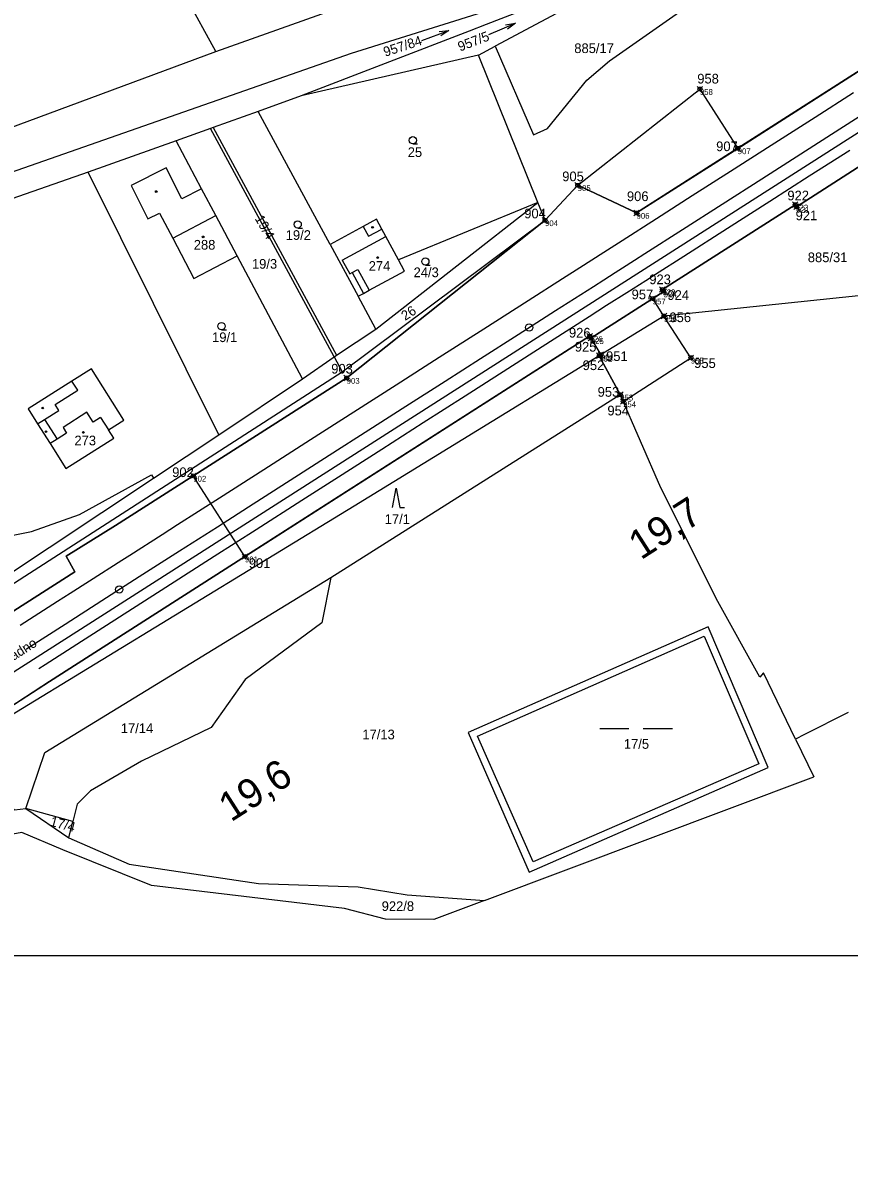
# Model space of a CAD drawing. Extents: x -752184 to -751416, y -1028299 to -1027836.
# Drawn here: x -751817.4 to -751646.8, y -1028233.3 to -1027995.9 of the extents above; entities that cross this region are included whole.
import ezdxf

# ---------------------------------------------------------------- set-up
doc = ezdxf.new("R2010")
doc.units = 0
for name, color, linetype in [('02_Osa_koleje', 7, 'Continuous'), ('03_Staničení', 7, 'Continuous'), ('Dočasné zábory', 7, 'Continuous'), ('Obvod stavby', 7, 'Continuous'), ('Vrstva 4', 7, 'Continuous'), ('Vrstva 53', 7, 'Continuous'), ('Vrstva 55', 7, 'Continuous'), ('Vrstva 56', 7, 'Continuous'), ('Vrstva 57', 7, 'Continuous'), ('Vrstva 58', 7, 'Continuous'), ('Vrstva 59', 7, 'Continuous'), ('Vrstva 60', 7, 'Continuous'), ('Vrstva 63', 7, 'Continuous'), ('VYT-BODY', 7, 'Continuous')]:
    doc.layers.add(name, color=color, linetype=linetype)

msp = doc.modelspace()

# ---------------------------------------------------------------- linework, layer by layer
at = {"layer": '02_Osa_koleje'}
for p, q in [((-751653.82, -1028015.29), (-751645.91, -1028010.23)), ((-751648.69, -1028017.73), (-751640.92, -1028012.76)), ((-751662.87, -1028021.07), (-751653.82, -1028015.29)), ((-751656.74, -1028022.88), (-751648.69, -1028017.73)), ((-751671.32, -1028026.46), (-751662.87, -1028021.07)), ((-751664.8, -1028028.03), (-751656.74, -1028022.88)), ((-751655.05, -1028027.47), (-751646.64, -1028022.11)), ((-751679.23, -1028031.51), (-751671.32, -1028026.46)), ((-751663.19, -1028032.68), (-751655.05, -1028027.47)), ((-751673, -1028033.27), (-751664.8, -1028028.03)), ((-751686.59, -1028036.23), (-751679.23, -1028031.51)), ((-751671.92, -1028038.25), (-751663.19, -1028032.68)), ((-751681.21, -1028038.52), (-751673, -1028033.27)), ((-751693.69, -1028040.78), (-751686.59, -1028036.23)), ((-751688.98, -1028043.49), (-751681.21, -1028038.52)), ((-751680.91, -1028044.01), (-751671.92, -1028038.25)), ((-751697.47, -1028043.2), (-751693.69, -1028040.78)), ((-751702.42, -1028046.37), (-751697.47, -1028043.2)), ((-751691.1, -1028044.85), (-751688.98, -1028043.49)), ((-751686.82, -1028047.78), (-751680.91, -1028044.01)), ((-751705.97, -1028048.65), (-751702.42, -1028046.37)), ((-751695.1, -1028047.41), (-751693.57, -1028046.42)), ((-751693.57, -1028046.42), (-751691.1, -1028044.85)), ((-751713.11, -1028053.22), (-751705.97, -1028048.65)), ((-751699.61, -1028050.29), (-751697.44, -1028048.9)), ((-751697.44, -1028048.9), (-751695.1, -1028047.41)), ((-751692.69, -1028051.52), (-751688.81, -1028049.05)), ((-751688.81, -1028049.05), (-751686.82, -1028047.78)), ((-751707.41, -1028055.27), (-751699.61, -1028050.29)), ((-751696.88, -1028054.2), (-751692.69, -1028051.52)), ((-751722.23, -1028059.04), (-751713.11, -1028053.22)), ((-751715.15, -1028060.22), (-751707.41, -1028055.27)), ((-751700.46, -1028056.5), (-751696.88, -1028054.2)), ((-751708.45, -1028061.62), (-751700.46, -1028056.5)), ((-751731.44, -1028064.93), (-751722.23, -1028059.04)), ((-751722.91, -1028065.18), (-751715.15, -1028060.22)), ((-751717.26, -1028067.26), (-751708.45, -1028061.62)), ((-751740.37, -1028070.64), (-751731.44, -1028064.93)), ((-751730.24, -1028069.87), (-751722.91, -1028065.18)), ((-751726.12, -1028072.93), (-751717.26, -1028067.26)), ((-751749.1, -1028076.23), (-751740.37, -1028070.64)), ((-751738.35, -1028075.06), (-751730.24, -1028069.87)), ((-751734.76, -1028078.44), (-751726.12, -1028072.93)), ((-751746.01, -1028079.96), (-751738.35, -1028075.06)), ((-751758.04, -1028081.94), (-751749.1, -1028076.23)), ((-751754.17, -1028085.18), (-751746.01, -1028079.96)), ((-751743.32, -1028083.91), (-751734.76, -1028078.44)), ((-751767.69, -1028088.11), (-751758.04, -1028081.94)), ((-751752.24, -1028089.62), (-751743.32, -1028083.91)), ((-751762.21, -1028090.32), (-751754.17, -1028085.18)), ((-751776.82, -1028093.96), (-751767.69, -1028088.11)), ((-751759.86, -1028094.49), (-751752.24, -1028089.62)), ((-751769.91, -1028095.24), (-751762.21, -1028090.32)), ((-751785.51, -1028099.52), (-751776.82, -1028093.96)), ((-751777.26, -1028099.94), (-751769.91, -1028095.24)), ((-751769.24, -1028100.51), (-751759.86, -1028094.49)), ((-751795.35, -1028105.81), (-751788.71, -1028101.56)), ((-751788.71, -1028101.56), (-751785.51, -1028099.52)), ((-751785.09, -1028104.95), (-751777.26, -1028099.94)), ((-751777.92, -1028106.05), (-751769.24, -1028100.51)), ((-751796.99, -1028106.86), (-751795.35, -1028105.81)), ((-751793.41, -1028110.27), (-751785.09, -1028104.95)), ((-751787.91, -1028112.43), (-751777.92, -1028106.05)), ((-751803.67, -1028111.13), (-751796.99, -1028106.86)), ((-751801.11, -1028115.2), (-751793.41, -1028110.27)), ((-751807.69, -1028113.7), (-751803.67, -1028111.13)), ((-751797.49, -1028118.58), (-751787.91, -1028112.43)), ((-751818.04, -1028120.32), (-751810.27, -1028115.34)), ((-751810.27, -1028115.35), (-751807.69, -1028113.7)), ((-751808.72, -1028120.07), (-751801.11, -1028115.2)), ((-751816.72, -1028125.18), (-751808.72, -1028120.07)), ((-751806.31, -1028124.21), (-751797.49, -1028118.58)), ((-751816.74, -1028125.19), (-751816.72, -1028125.18)), ((-751812.84, -1028128.4), (-751806.31, -1028124.21)), ((-751814.16, -1028129.24), (-751812.84, -1028128.4))]:
    msp.add_line(p, q, dxfattribs=at)
at = {"layer": '03_Staničení'}
for centre in [(-751712.88, -1028058.77), (-751797.54, -1028112.91)]:
    msp.add_circle(centre, 0.75, dxfattribs=at)
at = {"layer": 'Dočasné zábory'}
for points in [[(-751702.85, -1028029.39), (-751677.63, -1028009.51), (-751669.8, -1028021.76)], [(-751700.15, -1028061), (-751698.06, -1028064.4), (-751698.4, -1028064.61), (-751694.07, -1028072.66), (-751693.47, -1028074.05), (-751679.48, -1028065.03), (-751685.04, -1028056.42), (-751687.36, -1028052.8)]]:
    msp.add_lwpolyline(points, dxfattribs=at)
at = {"layer": 'Obvod stavby'}
msp.add_lwpolyline([(-751644.14, -1028025.2), (-751657.66, -1028033.82), (-751657.93, -1028033.4), (-751685.36, -1028050.92), (-751685.1, -1028051.35), (-751700.15, -1028061), (-751700.39, -1028060.59), (-751771.59, -1028106.11), (-751782.26, -1028089.44), (-751750.57, -1028069.21), (-751709.61, -1028036.63), (-751702.85, -1028029.39), (-751690.7, -1028035.11), (-751669.8, -1028021.76), (-751634.83, -1027999.42)], dxfattribs=at)
at = {"layer": 'Vrstva 4'}
msp.add_lwpolyline([(-751880.79, -1027897.6), (-751466.79, -1027897.6), (-751466.79, -1028188.6), (-751880.79, -1028188.6)], close=True, dxfattribs=at)
at = {"layer": 'Vrstva 53'}
for points in [[(-751934.1, -1028186.19), (-751914.9, -1028176.41), (-751903.43, -1028170.23), (-751901.96, -1028169.44), (-751904.77, -1028166.14), (-751893.52, -1028163.47), (-751890.97, -1028163.13), (-751806.75, -1028109.29), (-751808.53, -1028106.05), (-751798.29, -1028099.68), (-751750.57, -1028069.21), (-751709.61, -1028036.63), (-751702.85, -1028029.39), (-751690.7, -1028035.11), (-751634.83, -1027999.42), (-751532.07, -1027933.64), (-751519.82, -1027926.47), (-751506.87, -1027919.58), (-751494.13, -1027913.25), (-751481.54, -1027906.54), (-751469.19, -1027899.14), (-751466.79, -1027897.6)], [(-751644.14, -1028025.2), (-751657.66, -1028033.82), (-751657.93, -1028033.4), (-751685.36, -1028050.92), (-751685.1, -1028051.35), (-751700.15, -1028061), (-751700.39, -1028060.59), (-751811.98, -1028131.93), (-751832.08, -1028145), (-751819.17, -1028158.43), (-751842.96, -1028162.99), (-751863.83, -1028164.81), (-751866.87, -1028174.68), (-751861.84, -1028173.32), (-751837.73, -1028166.78), (-751864.36, -1028191.47), (-751928.16, -1028233.3)]]:
    msp.add_lwpolyline(points, dxfattribs=at)
at = {"layer": 'Vrstva 55'}
for p, q in [((-751777.61, -1028001.77), (-751795.36, -1027969.33)), ((-751777.61, -1028001.77), (-751721.34, -1027981.66)), ((-751684.34, -1027981.6), (-751719.87, -1028000.62)), ((-751830.33, -1028021.31), (-751777.61, -1028001.77)), ((-751723.32, -1028002.47), (-751719.87, -1028000.62)), ((-751723.32, -1028002.47), (-751759.96, -1028010.88)), ((-751711.11, -1028032.94), (-751723.32, -1028002.47)), ((-751759.96, -1028010.88), (-751768.84, -1028014.13)), ((-751768.84, -1028014.13), (-751778.12, -1028017.44)), ((-751754, -1028041.6), (-751768.84, -1028014.13)), ((-751778.69, -1028017.64), (-751785.81, -1028020.18)), ((-751778.12, -1028017.44), (-751778.69, -1028017.64)), ((-751753.17, -1028064.84), (-751778.69, -1028017.64)), ((-751778.12, -1028017.44), (-751752.67, -1028064.5)), ((-751785.81, -1028020.18), (-751803.99, -1028026.65)), ((-751780.53, -1028030.11), (-751785.81, -1028020.18)), ((-751803.99, -1028026.65), (-751859.41, -1028046.14)), ((-751777.01, -1028080.95), (-751803.99, -1028026.65)), ((-751780.53, -1028030.11), (-751784.62, -1028032.2)), ((-751702.85, -1028029.39), (-751709.61, -1028036.63)), ((-751744.55, -1028059.1), (-751711.11, -1028032.94)), ((-751711.11, -1028032.94), (-751739.87, -1028044.82)), ((-751709.61, -1028036.63), (-751711.11, -1028032.94)), ((-751751.51, -1028067.92), (-751709.61, -1028036.63)), ((-751709.61, -1028036.63), (-751750.57, -1028069.21)), ((-751754, -1028041.6), (-751748.2, -1028052.33)), ((-751759.72, -1028069.4), (-751773.17, -1028043.99)), ((-751744.55, -1028059.1), (-751748.2, -1028052.33)), ((-751752.67, -1028064.5), (-751744.55, -1028059.1)), ((-751759.72, -1028069.4), (-751753.17, -1028064.84)), ((-751753.17, -1028064.84), (-751752.67, -1028064.5)), ((-751753.17, -1028064.84), (-751751.51, -1028067.92)), ((-751694.07, -1028072.66), (-751698.4, -1028064.61)), ((-751777.01, -1028080.95), (-751759.72, -1028069.4)), ((-751753.83, -1028110.42), (-751694.07, -1028072.66)), ((-751790.46, -1028089.89), (-751777.01, -1028080.95)), ((-751825.11, -1028112.91), (-751790.46, -1028089.89)), ((-751832.08, -1028145), (-751811.98, -1028131.93)), ((-751657.84, -1028143.83), (-751654.06, -1028151.61)), ((-751722.1, -1028177.18), (-751654.06, -1028151.61)), ((-751819.17, -1028158.43), (-751816.81, -1028158.16)), ((-751807.12, -1028160.84), (-751816.81, -1028158.16)), ((-751816.81, -1028158.16), (-751807.94, -1028164.26)), ((-751807.94, -1028164.26), (-751807.12, -1028160.84)), ((-751722.1, -1028177.18), (-751732.54, -1028181.1)), ((-751732.54, -1028181.1), (-751742.53, -1028181.08))]:
    msp.add_line(p, q, dxfattribs=at)
for points in [[(-751469.19, -1027899.14), (-751481.54, -1027906.54), (-751494.13, -1027913.25), (-751506.87, -1027919.58), (-751519.82, -1027926.47), (-751532.07, -1027933.64), (-751634.83, -1027999.42), (-751690.7, -1028035.11), (-751702.85, -1028029.39)], [(-751865.7, -1028042.71), (-751749.56, -1028002.08), (-751713.49, -1027990.7), (-751668.79, -1027968.97)], [(-751684.34, -1027981.6), (-751721.79, -1027996.16), (-751725.3, -1027997.51), (-751759.96, -1028010.88)], [(-751719.87, -1028000.62), (-751712.01, -1028018.94), (-751709.09, -1028017.63), (-751700.97, -1028007.7), (-751696.27, -1028003.7), (-751679.08, -1027991.59)], [(-751811.98, -1028131.93), (-751700.39, -1028060.59), (-751700.15, -1028061), (-751685.1, -1028051.35), (-751685.36, -1028050.92), (-751657.93, -1028033.4), (-751657.66, -1028033.82), (-751644.14, -1028025.2)], [(-751784.62, -1028032.2), (-751787.87, -1028025.82), (-751795.1, -1028029.46), (-751791.61, -1028036.31), (-751789.26, -1028035.12), (-751786.51, -1028040.34)], [(-751597.31, -1028027.06), (-751634.36, -1028051.12), (-751685.04, -1028056.42), (-751698.4, -1028064.61)], [(-751773.17, -1028043.99), (-751777.58, -1028035.66), (-751780.53, -1028030.11)], [(-751739.87, -1028044.82), (-751742.48, -1028039.98), (-751743.32, -1028038.44), (-751744.41, -1028036.42), (-751747.18, -1028037.91), (-751754, -1028041.6)], [(-751786.51, -1028040.34), (-751782.14, -1028048.67), (-751773.17, -1028043.99)], [(-751748.2, -1028052.33), (-751747.12, -1028051.75), (-751745.92, -1028051.1), (-751738.61, -1028047.15), (-751739.87, -1028044.82)], [(-751698.4, -1028064.61), (-751729.61, -1028083.77), (-751749, -1028095.68), (-751820.32, -1028139.23), (-751832.08, -1028145)], [(-751884.03, -1028148.84), (-751854.09, -1028134.41), (-751824.25, -1028114.78), (-751751.51, -1028067.92)], [(-751807.31, -1028069.85), (-751816.38, -1028075.6), (-751814.4, -1028078.72), (-751811.83, -1028082.78), (-751808.57, -1028087.93), (-751798.69, -1028081.67), (-751799.78, -1028079.96), (-751796.57, -1028077.93), (-751803.3, -1028067.31), (-751807.31, -1028069.85)], [(-751750.57, -1028069.21), (-751798.29, -1028099.68), (-751808.53, -1028106.05), (-751806.75, -1028109.29), (-751890.97, -1028163.13), (-751893.52, -1028163.47)], [(-751657.84, -1028143.83), (-751664.47, -1028130.17), (-751665.22, -1028131.05), (-751673.89, -1028115.42), (-751685.71, -1028091.93), (-751694.07, -1028072.66)], [(-751829.79, -1028103.79), (-751815.64, -1028100.96), (-751805.78, -1028097.41), (-751790.88, -1028089.26), (-751790.46, -1028089.89)], [(-751816.81, -1028158.16), (-751812.9, -1028146.59), (-751753.83, -1028110.42)], [(-751753.83, -1028110.42), (-751755.69, -1028119.78), (-751771.54, -1028131.54), (-751778.55, -1028141.46), (-751792.98, -1028148.4), (-751803.51, -1028154.54), (-751806.26, -1028157.26), (-751807.12, -1028160.84)], [(-751663.5, -1028149.71), (-751675.94, -1028120.67), (-751725.5, -1028142.46), (-751712.88, -1028171.35), (-751663.5, -1028149.71)], [(-751647, -1028138.31), (-751656, -1028142.89), (-751657.84, -1028143.83)], [(-751742.53, -1028181.08), (-751751.04, -1028178.81), (-751790.89, -1028174.07), (-751809.18, -1028166.74), (-751817.68, -1028163.14), (-751837.73, -1028166.78)], [(-751807.94, -1028164.26), (-751795.47, -1028169.71), (-751768.76, -1028173.66), (-751748.19, -1028174.34), (-751738.05, -1028176.01), (-751722.1, -1028177.18)]]:
    msp.add_lwpolyline(points, dxfattribs=at)
at = {"layer": 'Vrstva 56'}
for p, q in [((-751786.51, -1028040.34), (-751777.58, -1028035.66)), ((-751747.18, -1028037.91), (-751746.09, -1028039.94)), ((-751746.09, -1028039.94), (-751743.32, -1028038.44)), ((-751751.47, -1028044.84), (-751742.48, -1028039.98)), ((-751751.47, -1028044.84), (-751749.93, -1028047.7)), ((-751749.45, -1028047.44), (-751748.25, -1028046.79)), ((-751748.25, -1028046.79), (-751745.92, -1028051.1)), ((-751749.93, -1028047.7), (-751749.45, -1028047.44)), ((-751749.45, -1028047.44), (-751747.12, -1028051.75)), ((-751806.11, -1028071.75), (-751807.31, -1028069.85)), ((-751810.79, -1028074.72), (-751806.11, -1028071.75)), ((-751810.02, -1028075.95), (-751810.79, -1028074.72)), ((-751814.4, -1028078.72), (-751812.97, -1028077.81)), ((-751812.97, -1028077.81), (-751810.02, -1028075.95)), ((-751812.97, -1028077.81), (-751810.4, -1028081.87)), ((-751804.21, -1028076.3), (-751809.16, -1028079.43)), ((-751802.93, -1028078.33), (-751804.21, -1028076.3)), ((-751801.41, -1028077.37), (-751802.93, -1028078.33)), ((-751801.41, -1028077.37), (-751799.78, -1028079.96)), ((-751809.16, -1028079.43), (-751808.41, -1028080.61)), ((-751810.4, -1028081.87), (-751811.83, -1028082.78)), ((-751808.41, -1028080.61), (-751810.4, -1028081.87)), ((-751723.57, -1028143.22), (-751676.75, -1028122.56)), ((-751676.75, -1028122.56), (-751665.43, -1028148.92)), ((-751712.04, -1028169.17), (-751723.57, -1028143.22)), ((-751665.43, -1028148.92), (-751712.04, -1028169.17))]:
    msp.add_line(p, q, dxfattribs=at)
at = {"layer": 'Vrstva 58'}
for p, q in [((-751721.24, -1027998.21), (-751715.7, -1027995.9)), ((-751735.07, -1027999.45), (-751729.44, -1027997.38)), ((-751736.92, -1028020.84), (-751735.92, -1028020.84)), ((-751760.69, -1028038.22), (-751759.69, -1028038.22)), ((-751734.32, -1028045.89), (-751733.32, -1028045.89)), ((-751776.42, -1028059.25), (-751775.42, -1028059.25)), ((-751698.31, -1028141.68), (-751692.31, -1028141.68)), ((-751689.31, -1028141.68), (-751683.31, -1028141.68))]:
    msp.add_line(p, q, dxfattribs=at)
for points in [[(-751717.74, -1027996.21), (-751715.7, -1027995.9), (-751717.36, -1027997.13)], [(-751731.49, -1027997.61), (-751729.44, -1027997.38), (-751731.14, -1027998.54)], [(-751741.12, -1028095.98), (-751740.37, -1028091.98), (-751739.62, -1028095.98), (-751738.62, -1028095.98)]]:
    msp.add_lwpolyline(points, dxfattribs=at)
for centre in [(-751736.92, -1028020.09), (-751760.69, -1028037.47), (-751734.32, -1028045.14), (-751776.42, -1028058.5)]:
    msp.add_circle(centre, 0.75, dxfattribs=at)
at = {"layer": 'Vrstva 59'}
for centre in [(-751789.9, -1028030.69), (-751745.22, -1028038.07), (-751780.23, -1028040.05), (-751744.16, -1028044.32), (-751813.36, -1028075.42), (-751812.67, -1028080.3), (-751804.96, -1028080.47)]:
    msp.add_circle(centre, 0.175, dxfattribs=at)
at = {"layer": 'Vrstva 60'}
for p, q in [((-751677.62, -1028009.51), (-751677.62, -1028009.51)), ((-751669.8, -1028021.76), (-751669.8, -1028021.76)), ((-751702.85, -1028029.39), (-751702.85, -1028029.39)), ((-751690.7, -1028035.11), (-751690.7, -1028035.11)), ((-751657.93, -1028033.4), (-751657.93, -1028033.4)), ((-751657.66, -1028033.82), (-751657.66, -1028033.82)), ((-751709.61, -1028036.63), (-751709.61, -1028036.63)), ((-751685.36, -1028050.92), (-751685.36, -1028050.92)), ((-751685.1, -1028051.35), (-751685.1, -1028051.35)), ((-751687.36, -1028052.8), (-751687.36, -1028052.8)), ((-751685.04, -1028056.42), (-751685.04, -1028056.42)), ((-751700.39, -1028060.59), (-751700.39, -1028060.59)), ((-751700.15, -1028061), (-751700.15, -1028061)), ((-751698.4, -1028064.61), (-751698.4, -1028064.61)), ((-751698.06, -1028064.4), (-751698.06, -1028064.4)), ((-751679.48, -1028065.03), (-751679.48, -1028065.03)), ((-751750.57, -1028069.21), (-751750.57, -1028069.21)), ((-751694.07, -1028072.66), (-751694.07, -1028072.66)), ((-751693.47, -1028074.05), (-751693.47, -1028074.05)), ((-751782.26, -1028089.44), (-751782.26, -1028089.44)), ((-751771.59, -1028106.11), (-751771.59, -1028106.11))]:
    msp.add_line(p, q, dxfattribs=at)
at = {"layer": 'Vrstva 63'}
msp.add_line((-751551.77, -1027958.95), (-751975.84, -1028230), dxfattribs=at)
at = {"layer": 'VYT-BODY'}
for p, q in [((-751677.06, -1028008.95), (-751678.19, -1028010.08)), ((-751677.06, -1028010.08), (-751678.19, -1028008.95)), ((-751669.24, -1028022.33), (-751670.37, -1028021.19)), ((-751669.24, -1028021.2), (-751670.37, -1028022.33)), ((-751702.28, -1028028.82), (-751703.42, -1028029.96)), ((-751702.28, -1028029.96), (-751703.42, -1028028.82)), ((-751690.13, -1028034.54), (-751691.27, -1028035.68)), ((-751690.13, -1028035.68), (-751691.27, -1028034.54)), ((-751657.36, -1028032.83), (-751658.5, -1028033.97)), ((-751657.36, -1028033.97), (-751658.5, -1028032.83)), ((-751657.09, -1028033.25), (-751658.23, -1028034.39)), ((-751657.09, -1028034.39), (-751658.23, -1028033.25)), ((-751709.04, -1028036.06), (-751710.18, -1028037.2)), ((-751709.04, -1028037.2), (-751710.18, -1028036.06)), ((-751684.79, -1028050.35), (-751685.93, -1028051.49)), ((-751684.79, -1028051.49), (-751685.93, -1028050.35)), ((-751684.53, -1028050.78), (-751685.67, -1028051.92)), ((-751684.53, -1028051.92), (-751685.67, -1028050.78)), ((-751686.79, -1028052.23), (-751687.93, -1028053.37)), ((-751686.8, -1028053.37), (-751687.93, -1028052.23)), ((-751684.47, -1028055.85), (-751685.61, -1028056.99)), ((-751684.47, -1028056.99), (-751685.61, -1028055.85)), ((-751699.82, -1028060.02), (-751700.96, -1028061.16)), ((-751699.82, -1028061.16), (-751700.96, -1028060.02)), ((-751699.58, -1028060.43), (-751700.72, -1028061.57)), ((-751699.58, -1028061.57), (-751700.72, -1028060.43)), ((-751697.83, -1028064.04), (-751698.97, -1028065.18)), ((-751697.83, -1028065.18), (-751698.97, -1028064.04)), ((-751697.5, -1028063.84), (-751698.63, -1028064.97)), ((-751697.5, -1028064.97), (-751698.63, -1028063.84)), ((-751678.92, -1028064.47), (-751680.05, -1028065.6)), ((-751678.92, -1028065.6), (-751680.05, -1028064.47)), ((-751750, -1028068.64), (-751751.14, -1028069.78)), ((-751750, -1028069.78), (-751751.14, -1028068.64)), ((-751693.5, -1028072.09), (-751694.64, -1028073.23)), ((-751693.5, -1028073.23), (-751694.64, -1028072.09)), ((-751692.9, -1028073.49), (-751694.03, -1028074.62)), ((-751692.9, -1028074.62), (-751694.03, -1028073.49)), ((-751781.69, -1028088.88), (-751782.82, -1028090.01)), ((-751781.69, -1028090.01), (-751782.82, -1028088.88)), ((-751771.02, -1028105.54), (-751772.15, -1028106.67)), ((-751771.02, -1028106.67), (-751772.15, -1028105.54))]:
    msp.add_line(p, q, dxfattribs=at)
for centre in [(-751677.62, -1028009.51), (-751669.8, -1028021.76), (-751702.85, -1028029.39), (-751690.7, -1028035.11), (-751657.93, -1028033.4), (-751657.66, -1028033.82), (-751709.61, -1028036.63), (-751685.36, -1028050.92), (-751685.1, -1028051.35), (-751687.36, -1028052.8), (-751685.04, -1028056.42), (-751700.39, -1028060.59), (-751700.15, -1028061), (-751698.4, -1028064.61), (-751698.06, -1028064.4), (-751679.48, -1028065.03), (-751750.57, -1028069.21), (-751694.07, -1028072.66), (-751693.47, -1028074.05), (-751782.26, -1028089.44), (-751771.59, -1028106.11)]:
    msp.add_circle(centre, 0.4, dxfattribs=at)

# ---------------------------------------------------------------- texts
at = {"layer": '02_Osa_koleje'}
msp.add_text('TÚ 0811 směr Kladno', height=2, rotation=32.6028, dxfattribs=at).set_placement((-751836.27, -1028138.5))
at = {"layer": '03_Staničení'}
for s, rotation, p in [('19,7', 32.5978, (-751689.82, -1028106.93)), ('19,6', 32.6004, (-751774.48, -1028161.08))]:
    msp.add_text(s, height=6, rotation=rotation, dxfattribs=at).set_placement(p)
at = {"layer": 'Dočasné zábory'}
for s, p in [('958', (-751678.16, -1028008.36)), ('957', (-751691.72, -1028052.95)), ('956', (-751683.91, -1028057.67)), ('952', (-751701.83, -1028067.58)), ('951', (-751696.99, -1028065.71)), ('955', (-751678.8, -1028067.15)), ('953', (-751698.74, -1028073.09)), ('954', (-751696.72, -1028076.95))]:
    msp.add_text(s, height=2, dxfattribs=at).set_placement(p)
at = {"layer": 'Obvod stavby'}
for s, p in [('907', (-751674.26, -1028022.34)), ('905', (-751706.05, -1028028.55)), ('906', (-751692.69, -1028032.66)), ('922', (-751659.55, -1028032.51)), ('904', (-751713.9, -1028036.22)), ('921', (-751657.85, -1028036.61)), ('923', (-751688.07, -1028049.83)), ('924', (-751684.32, -1028053.08)), ('926', (-751704.66, -1028060.86)), ('925', (-751703.45, -1028063.76)), ('903', (-751753.76, -1028068.3)), ('902', (-751786.61, -1028089.69)), ('901', (-751770.79, -1028108.47))]:
    msp.add_text(s, height=2, dxfattribs=at).set_placement(p)
at = {"layer": 'Vrstva 57'}
for s, rotation, p in [('957/84', 18, (-751742.62, -1028002.85)), ('957/5', 21, (-751727.16, -1028001.77)), ('19/4', 299.3436, (-751769.61, -1028036.25)), ('26', 33, (-751738.49, -1028057.43)), ('17/4', 345, (-751811.96, -1028161.71))]:
    msp.add_text(s, height=2, rotation=rotation, dxfattribs=at).set_placement(p)
for s, p in [('885/17', (-751703.56, -1028002.07)), ('25', (-751737.96, -1028023.55)), ('19/2', (-751763.16, -1028040.68)), ('288', (-751782.15, -1028042.69)), ('19/3', (-751770.14, -1028046.63)), ('885/31', (-751655.33, -1028045.28)), ('274', (-751746.02, -1028047.07)), ('24/3', (-751736.75, -1028048.38)), ('19/1', (-751778.37, -1028061.79)), ('273', (-751806.8, -1028083.13)), ('17/1', (-751742.71, -1028099.38)), ('17/14', (-751797.22, -1028142.59)), ('17/13', (-751747.33, -1028143.88)), ('17/5', (-751693.32, -1028145.84)), ('922/8', (-751743.34, -1028179.36))]:
    msp.add_text(s, height=2, dxfattribs=at).set_placement(p)
at = {"layer": 'Vrstva 60'}
for s, p in [('958', (-751677.62, -1028010.71)), ('907', (-751669.8, -1028022.96)), ('905', (-751702.85, -1028030.59)), ('906', (-751690.7, -1028036.31)), ('922', (-751657.93, -1028034.6)), ('921', (-751657.66, -1028035.02)), ('904', (-751709.61, -1028037.83)), ('923', (-751685.36, -1028052.12)), ('924', (-751685.1, -1028052.55)), ('957', (-751687.36, -1028054)), ('956', (-751685.04, -1028057.62)), ('926', (-751700.39, -1028061.79)), ('925', (-751700.15, -1028062.2)), ('952', (-751698.4, -1028065.81)), ('951', (-751698.06, -1028065.6)), ('955', (-751679.48, -1028066.23)), ('903', (-751750.57, -1028070.41)), ('953', (-751694.07, -1028073.86)), ('954', (-751693.47, -1028075.25)), ('902', (-751782.26, -1028090.64)), ('901', (-751771.59, -1028107.31))]:
    msp.add_text(s, height=1.2, dxfattribs=at).set_placement(p)

doc.saveas('drawing.dxf')
